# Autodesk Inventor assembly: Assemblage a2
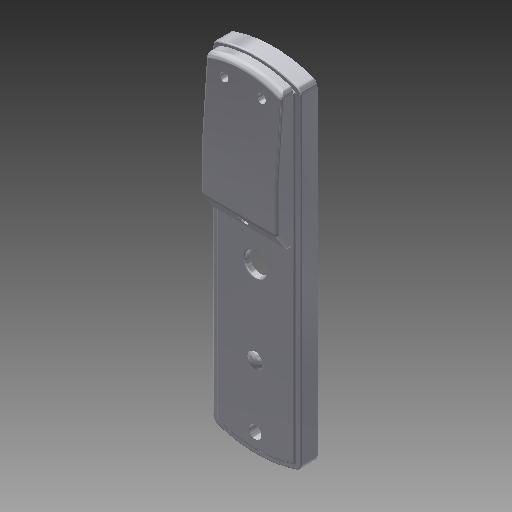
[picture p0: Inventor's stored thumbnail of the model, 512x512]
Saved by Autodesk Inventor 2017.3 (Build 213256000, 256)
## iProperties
Created: 2007-12
Part Number: Assemblage a2
Material: Générique
Document SubType Name: Assembly
Designer: ficho
Author: ficho
Sending System: SolidWorks 2009
Last Author: christophe
Last Saved: 2011-02-10
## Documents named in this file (12)
- G:\travail\année 2019-2020\réforme\toussaint\Serrure biométrique SET\Documentations_pedagogique\Modelisation_Solidworks\Assemblage a2.iam
- G:\travail\année 2019-2020\réforme\toussaint\Serrure biométrique SET\Documentations_pedagogique\Modelisation_Solidworks\piece a10.ipt
- G:\travail\année 2019-2020\réforme\toussaint\Serrure biométrique SET\Documentations_pedagogique\Modelisation_Solidworks\pièce a17.ipt
- G:\travail\année 2019-2020\réforme\toussaint\Serrure biométrique SET\Documentations_pedagogique\Modelisation_Solidworks\pièce a14.ipt
- G:\travail\année 2019-2020\réforme\toussaint\Serrure biométrique SET\Documentations_pedagogique\Modelisation_Solidworks\Pièce a11.ipt
- G:\travail\année 2019-2020\réforme\toussaint\Serrure biométrique SET\Documentations_pedagogique\Modelisation_Solidworks\piece a18.ipt
- G:\travail\année 2019-2020\réforme\toussaint\Serrure biométrique SET\Documentations_pedagogique\Modelisation_Solidworks\pièce a15.ipt
- G:\travail\année 2019-2020\réforme\toussaint\Serrure biométrique SET\Documentations_pedagogique\Modelisation_Solidworks\piece a20.ipt
- G:\travail\année 2019-2020\réforme\toussaint\Serrure biométrique SET\Documentations_pedagogique\Modelisation_Solidworks\pièce a22.ipt
- G:\travail\année 2019-2020\réforme\toussaint\Serrure biométrique SET\Documentations_pedagogique\Modelisation_Solidworks\piece a19.ipt
- G:\travail\année 2019-2020\réforme\toussaint\Serrure biométrique SET\Documentations_pedagogique\Modelisation_Solidworks\piece a21.ipt
- G:\travail\année 2019-2020\réforme\toussaint\Serrure biométrique SET\Documentations_pedagogique\Modelisation_Solidworks\Assemblage2^Assemblage a2.iam
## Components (21 placed, 11 different names)
1. piece a10:1
2. pièce a17:1
3. pièce a17:2
4. pièce a14:1
5. Pièce a11:1
6. piece a18:5
7. piece a18:6
8. piece a18:7
9. piece a18:8
10. pièce a15:2
11. piece a20:5
12. piece a20:6
13. piece a20:7
14. piece a20:8
15. pièce a22:1
16. piece a19:5
17. piece a19:6
18. piece a19:7
19. piece a21:2
20. piece a21:3
21. Assemblage2^Assemblage a2:1 [sub-assembly]
